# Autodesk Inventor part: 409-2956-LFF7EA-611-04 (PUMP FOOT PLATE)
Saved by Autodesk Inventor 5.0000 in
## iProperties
Created: 2010-06
Part Number: 409-2956-LFF7EA-611-04 (PUMP FOOT PLATE)
Cost Center: 0 lbmass
Material: A36 STEEL PLATE
Document SubType Name: Sheet Metal
Designer: S. Boerckel
Authority: 0 in^3
Mass: 5095.19 g
Surface Area: 1171.54 cm^2
Volume: 648.243 cm^3
Density: 7.86 g/cm^3
Flat Pattern Width: 12.7 cm
Flat Pattern Length: 40.64 cm
Flat Pattern Area: 516.128 cm^2
Sheet Metal Rule: 1/2"Thk
Sheet Metal Width: 16.0000 in
Sheet Metal Length: 80.0000 in^2
Description: PUMP FOOT PLATE
User Status: BURN
SaveDate: 2008-01-15
SaveTime: 10:24
FileName: Sheet Metal
Wide: =<Flat Pattern Width>cm
Length: =<Flat Pattern Length>cm
Thickness: 0.5000 in
SMR: =<Sheet Metal Rule> - <Material>
Author: S. Boerckel
Revision Number: 0
Subject: DEMIN WATER FORWARDING PUMP SKID-7EA
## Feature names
1. Hole1
2. Plate1
